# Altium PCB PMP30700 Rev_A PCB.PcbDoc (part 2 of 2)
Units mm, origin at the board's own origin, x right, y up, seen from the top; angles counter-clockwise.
Board outline 118.11 x 43.81 mm, 4 copper layers (Top Layer, Layer 1, Layer 2, Bottom Layer), stack 1.786 mm thick; 113 components, 51 nets, 253 pads, 184 vias.
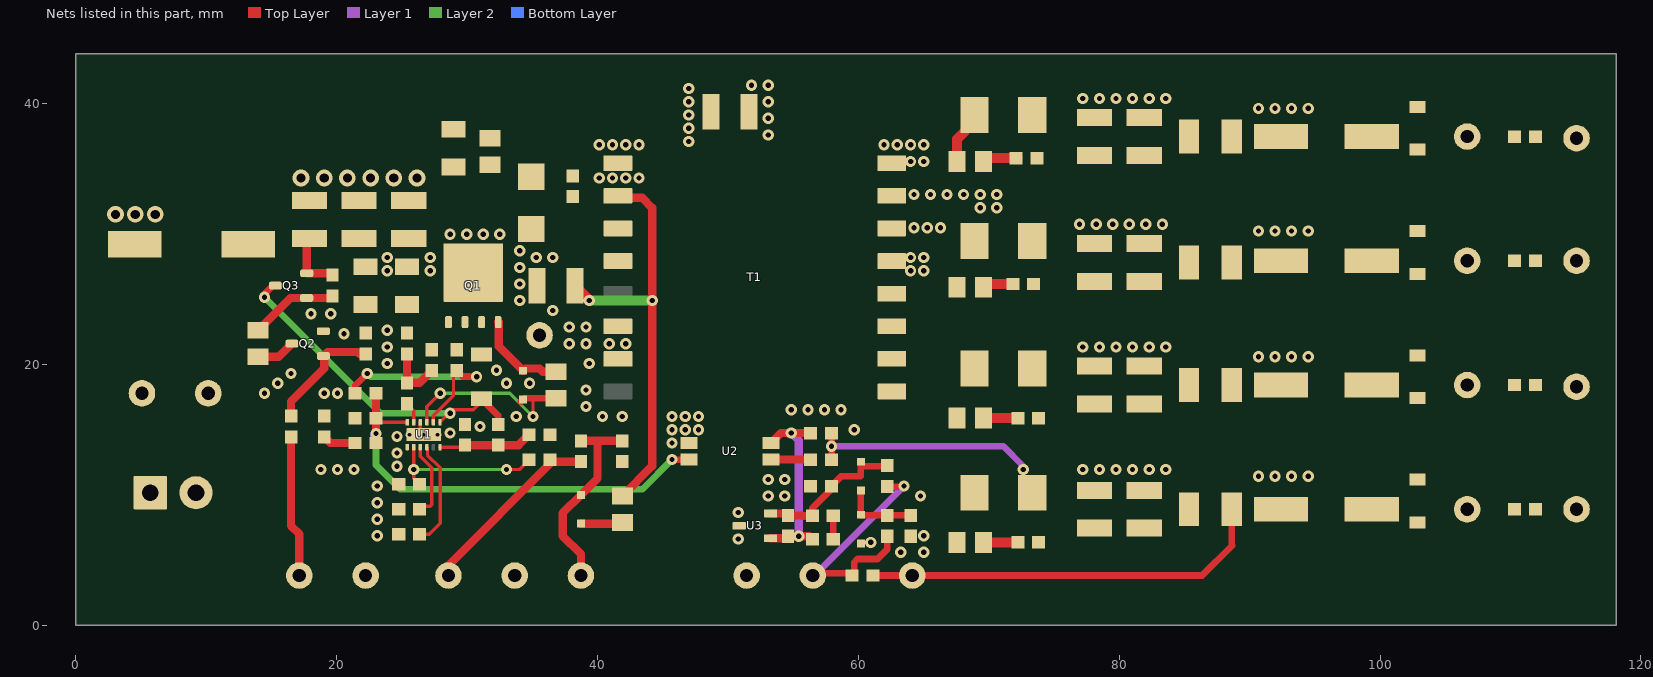
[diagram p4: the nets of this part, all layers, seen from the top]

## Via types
v1: diameter 0.864, hole 0.406, Top Layer to Bottom Layer, 159 vias
v2: diameter 0.864, hole 0.406, Top Layer to Bottom Layer, tented top, 13 vias
v3: diameter 1.27, hole 0.711, Top Layer to Bottom Layer, 9 vias
v4: diameter 0.6, hole 0.3, Top Layer to Bottom Layer, 3 vias

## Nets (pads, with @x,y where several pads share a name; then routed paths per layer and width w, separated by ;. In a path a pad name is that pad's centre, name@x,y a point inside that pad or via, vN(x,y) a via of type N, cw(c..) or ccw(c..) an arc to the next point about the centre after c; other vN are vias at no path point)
GND-P: C11.2 C12.2 C13.2 C14.2 C15.2 C23.2 C24.2 C30.2 C31.2 C32.2 C33.2 C37.2 C38.2 C39.2 J1.1 Q2.2 R12.1 R13.1 R14.1 R17.1 R19.1 R28.1 T1.1 TP1.1 TP14.1 TP16.1 U1.4 U1.7 U1.13@26.67,14.605 U2.3 | length 1.1
  Top Layer w0.254: U1.4@26.42,15.555 26.42,14.795 v4(26.67,14.605)
  other v1: 23.114,6.858 23.114,8.128 23.114,9.398 23.114,10.668 18.796,11.938 20.066,11.938 21.336,11.938 24.638,12.192 24.638,13.208 45.72,13.97 24.638,14.478 28.702,14.732 45.72,14.986 46.736,14.986 47.752,14.986 30.988,15.24 33.782,16.002 40.386,16.002 41.91,16.002 39.116,16.764 14.478,17.78 19.05,17.78 20.066,17.78 39.116,18.034 15.494,18.542 33.02,18.542 16.51,19.304 32.258,19.558 23.876,20.066 23.876,21.336 20.574,22.352 23.876,22.606 18.034,23.876 19.558,23.876 23.876,27.178 27.178,27.178 23.876,28.194 27.178,28.194 40.132,34.29 41.148,34.29 42.164,34.29 43.18,34.29 40.132,36.83 41.148,36.83 42.164,36.83 43.18,36.83 46.99,37.084 46.99,38.1 46.99,39.116 46.99,40.132 46.99,41.148
  other v2: 45.72,16.002 46.736,16.002 47.752,16.002 34.798,18.542
  other v3: 3.048,31.496 4.572,31.496 6.096,31.496 17.272,34.29 19.05,34.29 20.828,34.29 22.606,34.29 24.384,34.29 26.162,34.29
  other v4: 25.595,14.605 27.745,14.605
GND-S1: C2.2 C3.2 C4.2 C5.2 C39.1 D2.2 D15.2 R25.1 R26.1 RTN_1.1 T1.13 TP18.1 U3.3
  other v1: 63.246,5.588 65.024,5.588 60.96,6.35 50.8,6.604 65.024,6.858 50.8,8.636 53.086,9.906 54.356,9.906 64.77,9.906 53.086,11.176 54.356,11.176 90.678,11.43 91.948,11.43 93.218,11.43 94.488,11.43 77.216,11.938 78.486,11.938 79.756,11.938 81.026,11.938 82.296,11.938 83.566,11.938 59.69,14.986 65.024,27.178 65.024,28.194 53.086,37.592 53.086,38.862 53.086,40.132 51.816,41.402 53.086,41.402
  other v2: 54.864,16.51 56.134,16.51 57.404,16.51 58.674,16.51 64.008,27.178 64.008,28.194
NetC1_2: C1.2 R1.2 | length 2.6
  Top Layer w0.762: R1.2@69.596,6.35 C1.2@72.225,6.35
NetC6_1: C6.1 C7.1 C8.1 D3.1 L2.1
NetC6_2: C6.2 R2.2 | length 2.6
  Top Layer w0.762: R2.2@69.596,15.875 C6.2@72.225,15.875
NetC7_2: C7.2 C8.2 C9.2 C10.2 D4.2 RTN_2.1 T1.14
  other v1: 90.678,20.574 91.948,20.574 93.218,20.574 94.488,20.574 77.216,21.336 78.486,21.336 79.756,21.336 81.026,21.336 82.296,21.336 83.566,21.336 64.262,30.48 65.278,30.48 66.294,30.48
NetC9_1: C9.1 C10.1 D4.1 L2.2 OUT_2.1
NetC11_1: C11.1 C12.1 C13.1 C14.1 C15.1 C16.1 J1.2 Q3.2 R3.2 R6.1 T1.3 T1.4 TP5.1 | length 4.8
  Top Layer w0.635: C12.1@17.915,29.665 17.71,29.46 Q3.2@17.71,26.985 19.535,26.985 R6.1@19.685,26.835
NetC16_2: C16.2 D5.1 R3.1
NetC17_1: C17.1 D5.2 Q1.5 Q1.6 Q1.7 Q1.8 Q1.9@30.48,27.04 T1.6 T1.7 TP3.1
  other v1: 39.37,20.066 37.846,21.59 39.116,21.59 40.894,21.59 42.164,21.59 37.846,22.86 39.116,22.86 36.576,24.13 34.036,24.892 34.036,26.162 34.036,27.432 35.306,28.194 36.576,28.194 34.036,28.702 28.702,29.972 29.972,29.972 31.242,29.972 32.512,29.972
NetC17_2: C17.2 R5.2 T1.2 | length 32.7
  Top Layer w0.635: T1.2@41.302,32.92 T1.2@41.57,32.92 41.724,32.766 43.434,32.766 44.196,32.004 v2(44.196,24.892) 44.196,12.192 R5.2@41.91,9.906
  Top Layer w0.762: C17.2@38.28,26.035 39.37,24.945 v1(39.37,24.892)
  Layer 2 w0.762: v1(39.37,24.892) v2(44.196,24.892)
NetC18_1: C18.1 C19.1 C20.1 D6.1 L3.1
NetC18_2: C18.2 R4.2 | length 2.4
  Top Layer w0.762: R4.2@69.596,25.908 69.85,26.162 C18.2@71.844,26.162
NetC19_2: C19.2 C20.2 C21.2 C22.2 D7.2 RTN_3.1 T1.15
  other v1: 90.678,30.226 91.948,30.226 93.218,30.226 94.488,30.226 76.962,30.734 78.232,30.734 79.502,30.734 80.772,30.734 82.042,30.734 83.312,30.734 69.342,32.004 70.612,32.004 64.262,33.02 65.532,33.02 66.802,33.02 68.072,33.02 69.342,33.02 70.612,33.02
NetC21_1: C21.1 C22.1 D7.1 L3.2 OUT_3.1
NetC23_1: C23.1 D8.1 R15.2 TP13.1 | length 15.2
  Top Layer w0.635: TP13.1@38.735,3.81 38.735,5.461 37.338,6.858 37.338,8.593 D8.1@38.735,9.99 40.005,11.26 40.005,14.135 ; R15.2@38.735,14.135 40.005,14.135 ; C23.1@41.91,14.135 40.005,14.135
NetC24_1: C24.1 Q3.3 R7.2 U1.1 | length 25.6
  Top Layer w0.254: U1.1@27.92,15.555 v1@28.661,16.296 ; v1@28.875,16.51 30.48,16.51 31.115,17.145 C24.1@31.115,17.35
  Top Layer w0.508: v1(14.478,25.146) 14.478,25.4 15.113,26.035 Q3.3@15.31,26.035 ; C24.1@31.115,17.35 32.385,16.08 R7.2@32.385,15.405
  Layer 2 w0.508: v1(14.478,25.146) 23.368,16.256 v1(28.702,16.256)
  Bottom Layer w0.381: v1@28.662,16.297 v1(28.702,16.256) v1@28.676,16.23
NetC25_1: C25.1 C26.1 C27.1 D10.1 L4.1
NetC25_2: C25.2 R8.2 | length 2.6
  Top Layer w0.762: R8.2@69.596,35.814 C25.2@72.225,35.814
NetC26_2: C26.2 C27.2 C28.2 C29.2 D11.2 RTN_4.1 T1.16
  other v1: 64.008,35.56 65.024,35.56 61.976,36.83 62.992,36.83 64.008,36.83 65.024,36.83 90.678,39.624 91.948,39.624 93.218,39.624 94.488,39.624 77.216,40.386 78.486,40.386 79.756,40.386 81.026,40.386 82.296,40.386 83.566,40.386
NetC28_1: C28.1 C29.1 D11.1 L4.2 OUT_4.1
NetC31_1: C31.1 R10.1 R18.2 | length 4.5
  Top Layer w0.635: C31.1@25.4,20.79 R18.2@25.4,18.58 26.365,18.58 R10.1@27.305,19.52
NetC32_1: C32.1 R11.1 | length 2.6
  Top Layer w0.635: C32.1@19.05,14.44 19.52,13.97 R11.1@21.425,13.97
NetC33_1: C33.1 R11.2 R23.2 U1.6 U2.4 | length 34
  Top Layer w0.254: C33.1@23.025,15.875 23.345,15.555 U1.6@25.42,15.555
  Top Layer w0.508: v1(45.72,12.7) U2.4@47.015,12.7
  Top Layer w0.635: v2(23.025,14.695) C33.1@23.025,15.875 R23.2@23.025,17.78
  Layer 2 w0.508: v2(23.025,14.695) 23.025,12.281 24.892,10.414 43.434,10.414 v1(45.72,12.7)
  Bottom Layer w0.635: v2@22.86,14.53 v2(23.025,14.695)
NetC34_1: C34.1 R22.2 R27.1 TP19.1 | length 19.4
  Top Layer w0.508: TP19.1@56.515,3.81 56.68,3.975 R27.1@59.69,3.975 ; R27.1@59.525,3.81 R27.1@59.69,3.975 ; C34.1@62.23,6.82 62.23,5.842 61.468,5.08 59.944,5.08 59.69,4.826 R27.1@59.69,3.975 ; R22.2@62.23,10.63 63.462,10.63 v1(63.5,10.668)
  Layer 1 w0.508: TP19.1@56.515,3.81 56.642,3.81 v1(63.5,10.668)
NetC34_2: C34.2 D14.2 D15.1 R25.2 | length 5.7
  Top Layer w0.508: D14.2@60.198,10.33 D15.1@60.198,8.466 60.244,8.42 C34.2@62.23,8.42 R25.2@64.008,8.42
NetC35_1: C35.1 R21.1 R24.1 U2.2 U3.1 | length 14.9
  Top Layer w0.635: U3.1@53.27,6.67 54.46,6.67 C35.1@54.61,6.82 v1(55.435,6.82) 56.261,6.82 R24.1@56.477,6.604 ; U2.2@53.315,13.97 54.077,14.732 v1(54.864,14.732) R21.1@56.35,14.732
  Layer 1 w0.635: v1(54.864,14.732) 55.435,14.16 v1(55.435,6.82)
NetC35_2: C35.2 C36.2 D14.1 R22.1 R26.2 U3.2 | length 11.9
  Top Layer w0.508: C36.2@56.477,8.382 56.477,8.979 57.95,10.452 R26.2@57.95,10.668 58.712,11.43 60.198,11.43 60.198,12.192 ; D14.1@60.198,12.53 60.198,12.192 ; R22.1@62.23,12.23 62.192,12.192 60.198,12.192
  Top Layer w0.635: U3.2@53.27,8.57 54.46,8.57 C35.2@54.61,8.42 55.689,8.42 55.727,8.382 C36.2@56.477,8.382
NetC36_1: C36.1 R24.2 | length 1.8
  Top Layer w0.508: R24.2@58.077,6.604 C36.1@58.077,8.382
NetC37_1: C37.1 R7.1 R12.2 U1.12 | length 7.2
  Top Layer w0.254: U1.12@27.92,13.655 29.695,13.655 C37.1@29.845,13.805
  Top Layer w0.635: C37.1@29.845,13.805 R7.1@32.385,13.805 33.96,13.805 R12.2@34.76,14.605
NetC38_1: C38.1 U1.9 | length 5.9
  Top Layer w0.254: C38.1@26.365,8.89 26.585,9.11 27.192,9.11 27.305,9.223 27.305,12.065 26.42,12.95 U1.9@26.42,13.655
NetD1_2: D1.2 R1.1 T1.9
NetD3_2: D3.2 R2.1 T1.10
NetD6_2: D6.2 R4.1 T1.11
NetD8_2: D8.2 R5.1 | length 3.2
  Top Layer w0.635: D8.2@38.735,7.79 41.826,7.79 R5.1@41.91,7.874
NetD9_1: D9.1 R9.2 U1.3 | length 14.7
  Top Layer w0.254: U1.3@26.92,15.555 26.92,16.76 v1(27.94,17.78) ; v1(35.052,16.002) 35.052,17.386 35.065,17.399
  Top Layer w0.508: D9.1@34.12,17.145 D9.1@34.29,17.315 34.374,17.399 35.065,17.399 R9.2@36.83,17.399
  Layer 2 w0.254: v1(27.94,17.78) 33.274,17.78 v1(35.052,16.002)
NetD9_2: D9.2 Q1.4 R9.1 | length 7.3
  Top Layer w0.635: Q1.4@32.385,23.24 32.433,23.24 32.433,21.373 D9.2@34.29,19.515 34.46,19.685 35.56,19.685 35.814,19.431 R9.1@36.83,19.431
NetD10_2: D10.2 R8.1 T1.12 | length 3.6
  Top Layer w0.762: R8.1@67.564,35.56 67.564,37.262 D10.2@68.91,38.608
NetQ1_1: Q1.1 Q1.2 Q1.3 R10.2 R13.2 R28.2
NetQ2_1: Q2.1 R19.2 R30.1 | length 9.1
  Top Layer w0.635: R30.1@16.51,16.04 16.51,17.145 19.05,19.685 19.05,20.57 Q2.1@18.98,20.64 19.295,20.955 21.59,20.955 21.755,20.79 R19.2@22.225,20.79
NetQ2_3: Q2.3 R29.1 | length 3
  Top Layer w0.635: R29.1@13.97,20.574 15.554,20.574 16.57,21.59 Q2.3@16.58,21.59
NetQ3_1: Q3.1 R6.2 R29.2 | length 6.8
  Top Layer w0.635: R29.2@13.97,22.606 16.449,25.085 Q3.1@17.71,25.085 19.535,25.085 R6.2@19.685,25.235
NetR14_2: R14.2 U1.10 | length 8.2
  Top Layer w0.254: R14.2@26.365,6.985 27.115,6.985 27.94,7.81 27.94,12.072 26.968,13.044 26.968,13.607 U1.10@26.92,13.655
NetR15_1: R15.1 R16.2 TP12.1 | length 14.5
  Top Layer w0.635: TP12.1@28.575,3.81 28.575,4.585 R16.2@36.525,12.535 ; R16.2@36.36,12.7 R16.2@36.525,12.535 ; R15.1@38.735,12.535 R16.2@36.525,12.535
NetR16_1: R16.1 R17.2 U1.8 | length 12.2
  Top Layer w0.254: U1.8@25.92,13.655 v1(25.92,11.938) 25.92,11.24 R17.2@26.365,10.795 ; v1(33.02,11.938) 33.998,11.938 R16.1@34.76,12.7
  Layer 2 w0.254: v1(25.92,11.938) v1(33.02,11.938)
  Bottom Layer w0.254: v1@25.908,11.938 v1(25.92,11.938)
NetR18_1: R18.1 U1.5 | length 1.6
  Top Layer w0.254: R18.1@25.4,16.98 25.92,16.46 U1.5@25.92,15.555
NetR20_1: R20.1 U2.1 | length 3
  Top Layer w0.635: U2.1@53.315,12.7 R20.1@56.35,12.7
NetR30_2: R30.2 TP15.1 | length 10.9
  Top Layer w0.635: R30.2@16.51,14.44 16.51,7.62 17.145,6.985 TP15.1@17.145,3.81
OUT1_SW: C1.1 C2.1 C3.1 D1.1 L1.1 R20.2 R21.2 | length 17.6
  Top Layer w0.508: R20.2@57.95,12.7 v1(57.95,13.716) R21.2@57.95,14.732
  Layer 1 w0.508: v1(57.95,13.716) 71.12,13.716 72.644,12.192 v2(72.644,11.938)
OUT_1: C4.1 C5.1 D2.1 L1.2 OUT_1.1 R27.2 TP17.1 | length 31.3
  Top Layer w0.508: R27.2@61.125,3.81 TP17.1@64.135,3.81 86.36,3.81 88.646,6.096 88.635,6.107 L1.2@88.635,8.89
VCC: C30.1 R23.1 U1.2 | length 16.8
  Top Layer w0.254: U1.2@27.42,15.555 27.422,15.557 27.422,16.049 28.956,17.583 28.956,19.266 C30.1@29.21,19.52
  Top Layer w0.508: R23.1@21.425,17.78 21.425,18.377 v1(22.352,19.304) ; C30.1@29.21,19.52 29.68,19.05 v1(30.734,19.05)
  Layer 2 w0.508: v1(22.352,19.304) 22.606,19.05 v1(30.734,19.05)
pads on no net: Q1.9@29.03,25.655 Q1.9@29.03,27.435 Q1.9@30.48,25.655 Q1.9@30.48,26.585 Q1.9@30.48,27.435 Q1.9@31.93,25.655 Q1.9@31.93,27.435 T1.5 T1.8 U1.11 U1.13@25.985,14.605 U1.13@27.355,14.605

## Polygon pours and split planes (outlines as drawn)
GND-S1 on Top Layer "Top Layer-GND-S1" (solid, pour order 92): 52.324,36.576 51.054,37.846 51.054,42.164 55.88,42.164 56.642,41.402 56.642,22.606 60.452,22.606 60.452,14.478 61.95,12.98 62.955,12.98 65.532,10.403 65.532,2.54 50.038,2.54 49.53,3.048 49.53,9.144 52.324,11.938
NetD1_2 on Top Layer "Top Layer-NetD1_2" (solid, pour order 84): 61.468,18.542 63.754,18.542 64.516,17.78 64.516,14.986 67.31,12.192 70.612,12.192 70.612,8.636 70.104,8.128 68.58,8.128 68.326,7.874 68.326,5.334 66.7,5.334 66.548,5.486 66.548,10.922 61.468,16.002
GND-S1 on Top Layer "Top Layer-GND-S1 2" (solid, pour order 80): 61.468,28.702 65.278,28.702 65.532,28.448 65.532,26.67 64.008,26.67 63.5,27.178 61.468,27.178
NetD3_2 on Top Layer "Top Layer-NetD3_2" (solid, pour order 78): 61.468,21.082 70.866,21.082 71.12,20.828 71.12,17.78 70.866,17.526 68.58,17.526 68.326,17.272 68.326,15.24 68.072,14.986 66.548,14.986 66.548,18.034 65.024,19.558 61.468,19.558
NetD6_2 on Top Layer "Top Layer-NetD6_2" (solid, pour order 76): 61.468,23.622 64.516,23.622 66.802,25.908 66.802,28.194 67.818,29.21 67.818,30.734 71.12,30.734 71.12,27.432 70.866,27.178 68.326,27.178 68.072,26.924 68.072,24.638 65.532,22.098 61.468,22.098
NetD10_2 on Top Layer "Top Layer-NetD10_2" (solid, pour order 74): 69.85,40.64 70.104,40.386 70.104,37.592 69.85,37.338 66.294,37.338 65.532,38.1 60.198,38.1 59.944,37.846 59.944,26.416 60.198,26.162 63.5,26.162 63.5,24.892 58.42,24.892 57.912,25.4 57.912,39.624 58.928,40.64
NetC7_2 on Top Layer "Top Layer-NetC19_2" (solid, pour order 73): 66.802,30.988 66.802,29.718 65.024,29.718 61.468,29.718 61.468,30.988
NetC19_2 on Top Layer "Top Layer-NetC19_2" (solid, pour order 71): 70.866,33.528 71.374,33.02 71.374,31.496 68.58,31.496 67.818,32.258 61.468,32.258 61.468,33.528
NetC26_2 on Top Layer "Top Layer-NetC26_2" (solid, pour order 69): 61.468,34.798 61.468,37.592 65.278,37.592 65.532,37.338 65.532,34.798
NetC26_2 on Top Layer "Top Layer-NetC26_2 1" (solid, pour order 67): 89.916,39.624 90.17,39.37 90.17,36.576 90.424,36.322 94.234,36.322 94.742,36.83 94.742,39.116 95.25,39.624 101.6,39.624 102.108,39.116 104.394,39.116 105.156,39.878 110.49,39.878 111.252,39.116 111.252,34.798 112.014,34.036 116.078,34.036 116.332,34.29 116.332,40.64 115.824,41.148 76.708,41.148 76.2,40.64 76.2,38.1 83.312,38.1 83.566,38.354 83.566,39.116 84.074,39.624
NetC19_2 on Top Layer "Top Layer-NetC19_2 1" (solid, pour order 65): 89.916,29.972 90.17,29.718 90.17,26.924 90.424,26.67 94.234,26.67 94.742,27.178 94.742,29.464 95.25,29.972 101.6,29.972 102.108,29.464 104.394,29.464 105.156,30.226 110.49,30.226 111.252,29.464 111.252,25.146 112.014,24.384 116.078,24.384 116.332,24.638 116.332,30.988 115.824,31.496 76.708,31.496 76.2,30.988 76.2,28.448 83.312,28.448 83.566,28.702 83.566,29.464 84.074,29.972
NetC7_2 on Top Layer "Top Layer-NetC7_2" (solid, pour order 63): 89.916,20.574 90.17,20.32 90.17,17.526 90.424,17.272 94.234,17.272 94.742,17.78 94.742,20.066 95.25,20.574 101.6,20.574 102.108,20.066 104.394,20.066 105.156,20.828 110.49,20.828 111.252,20.066 111.252,15.748 112.014,14.986 116.078,14.986 116.332,15.24 116.332,21.59 115.824,22.098 76.708,22.098 76.2,21.59 76.2,19.05 83.312,19.05 83.566,19.304 83.566,20.066 84.074,20.574
GND-S1 on Top Layer "Top Layer-GND-S1 1" (solid, pour order 47): 89.916,11.176 90.17,10.922 90.17,8.128 90.424,7.874 94.234,7.874 94.742,8.382 94.742,10.668 95.25,11.176 101.6,11.176 102.108,10.668 104.394,10.668 105.156,11.43 110.49,11.43 111.252,10.668 111.252,6.35 112.014,5.588 116.078,5.588 116.332,5.842 116.332,12.192 115.824,12.7 76.708,12.7 76.2,12.192 76.2,9.652 83.312,9.652 83.566,9.906 83.566,10.668 84.074,11.176
NetC28_1 on Top Layer "Top Layer-NetC28_1" (solid, pour order 45): 87.122,38.862 87.376,39.116 89.662,39.116 89.662,36.068 94.996,36.068 95.25,36.322 95.25,38.608 95.758,39.116 101.346,39.116 101.854,38.608 104.648,38.608 105.41,39.37 110.236,39.37 110.744,38.862 110.744,35.56 109.22,34.036 87.63,34.036 87.122,34.544
NetC21_1 on Top Layer "Top Layer-NetC21_1" (solid, pour order 43): 87.122,29.21 87.376,29.464 89.662,29.464 89.662,26.416 94.996,26.416 95.25,26.67 95.25,28.956 95.758,29.464 101.346,29.464 101.854,28.956 104.648,28.956 105.41,29.718 110.236,29.718 110.744,29.21 110.744,25.908 109.22,24.384 87.63,24.384 87.122,24.892
OUT_1 on Top Layer "Top Layer-OUT_1" (solid, pour order 41): 87.122,10.414 87.376,10.668 89.662,10.668 89.662,7.62 94.996,7.62 95.25,7.874 95.25,10.16 95.758,10.668 101.346,10.668 101.854,10.16 104.648,10.16 105.41,10.922 110.236,10.922 110.744,10.414 110.744,7.112 109.22,5.588 87.63,5.588 87.122,6.096
NetC9_1 on Top Layer "Top Layer-NetC9_1" (solid, pour order 39): 87.122,19.812 87.376,20.066 89.662,20.066 89.662,17.018 94.996,17.018 95.25,17.272 95.25,19.558 95.758,20.066 101.346,20.066 101.854,19.558 104.648,19.558 105.41,20.32 110.236,20.32 110.744,19.812 110.744,16.51 109.22,14.986 87.63,14.986 87.122,15.494
NetC25_1 on Top Layer "Top Layer-NetC25_1" (solid, pour order 37): 72.263,40.894 75.565,40.894 75.819,40.64 75.819,37.592 83.947,37.592 84.201,37.846 84.201,38.862 84.455,39.116 86.36,39.116 86.614,38.862 86.614,34.544 86.106,34.036 73.533,34.036 73.279,34.29 73.279,35.814 72.263,36.83
NetC18_1 on Top Layer "Top Layer-NetC18_1" (solid, pour order 35): 72.136,31.547 75.133,31.547 75.692,30.988 75.692,27.94 83.82,27.94 84.074,28.194 84.074,29.21 84.328,29.464 86.36,29.464 86.614,29.21 86.614,24.892 86.106,24.384 73.406,24.384 73.152,24.638 73.152,26.162 72.136,27.178
NetC6_1 on Top Layer "Top Layer-NetC6_1" (solid, pour order 33): 72.263,21.844 75.565,21.844 75.819,21.59 75.819,18.542 83.947,18.542 84.201,18.796 84.201,19.812 84.455,20.066 86.36,20.066 86.614,19.812 86.614,15.494 86.106,14.986 73.533,14.986 73.279,15.24 73.279,16.764 72.263,17.78
OUT1_SW on Top Layer "Top Layer-OUT1_SW" (solid, pour order 31): 72.136,12.446 75.438,12.446 75.692,12.192 75.692,9.144 83.82,9.144 84.074,9.398 84.074,10.414 84.328,10.668 86.106,10.668 86.614,10.16 86.614,6.096 86.106,5.588 73.406,5.588 73.152,5.842 73.152,7.366 72.136,8.382
GND-P on Top Layer "Top Layer-GND-P" (solid, pour order 8): 2.286,28.194 2.286,32.512 6.858,32.512 6.858,28.194
GND-P on Top Layer "Top Layer-GND-P 2" (solid, pour order 22): 49.276,42.164 49.276,37.846 48.26,36.83 48.26,10.922 39.878,2.54 11.938,2.54 11.938,42.164
NetC16_2 on Top Layer "Top Layer-NetC16_2" (solid, pour order 14): 33.528,33.528 33.782,33.274 36.83,33.274 36.576,33.528 36.576,37.846 35.814,38.608 28.194,38.608 28.194,37.338 30.48,37.338 30.48,36.576 32.766,36.576 33.528,35.814
NetC11_1 on Top Layer "Top Layer-NetC11_1" (solid, pour order 12): 33.02,33.528 33.02,35.814 32.512,36.322 30.226,36.322 30.226,42.164 1.524,42.164 1.524,2.54 13.208,2.54 13.208,18.542 12.192,19.558 12.192,24.384 16.002,28.194 19.812,28.194 20.574,28.956 26.416,28.956 27.178,29.718 27.178,30.48 27.94,31.242 32.512,31.242 33.02,31.75 37.592,31.75 37.846,31.496 37.846,29.972 39.624,28.194 39.624,27.432 40.132,26.924 42.672,26.924 43.18,27.432 43.18,31.496 42.926,31.75 40.132,31.75 38.862,33.02 33.528,33.02
NetC17_1 on Top Layer "Top Layer-NetC17_1" (solid, pour order 0): 27.94,30.48 32.766,30.48 33.02,30.734 33.02,30.988 33.528,31.496 36.83,31.496 37.084,31.242 37.084,24.384 37.846,23.622 42.926,23.622 43.18,23.368 43.18,19.812 42.672,19.304 39.116,19.304 38.608,19.812 38.608,20.32 37.846,21.082 34.544,21.082 33.528,22.098 33.528,23.876 32.766,24.638 27.94,24.638
NetQ1_1 on Top Layer "TOP_LAYER_NETQ1_1_P010" (solid, pour order 10): 21.336,26.162 27.178,26.162 27.178,24.13 31.496,24.13 31.496,22.098 27.94,22.098 27.94,20.574 26.924,20.574 26.67,20.828 26.67,23.368 26.416,23.622 21.336,23.622
GND-S1 on Bottom Layer "Bottom Layer-GND-S1" (solid, pour order 61): 52.324,36.83 51.054,38.1 51.054,42.164 59.436,42.164 59.944,41.656 59.944,28.702 65.278,28.702 65.532,28.448 65.532,21.59 74.422,12.7 115.824,12.7 116.332,12.192 116.332,3.048 115.824,2.54 50.038,2.54 49.53,3.048 49.53,9.144 52.315,11.929 52.315,11.995 52.324,12.004
NetC7_2 on Bottom Layer "Bottom Layer-NetC7_2" (solid, pour order 59): 76.2,22.098 67.31,30.988 63.754,30.988 63.754,29.718 65.024,29.718 66.802,27.94 66.802,24.384 76.2,14.986 116.332,14.986 116.586,15.24 116.586,21.59 116.078,22.098
NetC19_2 on Bottom Layer "Bottom Layer-NetC19_2" (solid, pour order 57): 75.692,24.384 68.58,31.496 67.818,32.258 63.754,32.258 63.754,33.528 70.866,33.528 72.898,31.496 115.824,31.496 116.332,30.988 116.332,24.638 116.078,24.384
NetC26_2 on Bottom Layer "Bottom Layer-NetC26_2" (solid, pour order 55): 61.468,34.798 72.771,34.798 73.533,34.036 116.078,34.036 116.332,34.29 116.332,40.64 115.824,41.148 61.468,41.148
NetC17_1 on Bottom Layer "Top Layer-NetC17_1" (solid, pour order 4): 27.94,30.48 32.766,30.48 33.02,30.734 33.02,30.988 33.528,31.496 36.83,31.496 37.084,31.242 37.084,24.384 37.846,23.622 42.926,23.622 43.18,23.368 43.18,19.812 42.672,19.304 39.116,19.304 38.608,19.812 38.608,20.32 37.846,21.082 34.544,21.082 33.528,22.098 33.528,23.876 32.766,24.638 27.94,24.638
GND-P on Bottom Layer "Bottom Layer-GND-P" (solid, pour order 24): 1.524,42.164 48.26,42.164 48.26,20.32 48.26,10.922 39.878,2.54 1.524,2.54
NetC26_2 on Layer 1 "Bottom Layer-NetC26_2" (solid, pour order 102): 61.468,34.798 72.771,34.798 73.533,34.036 116.078,34.036 116.332,34.29 116.332,40.64 115.824,41.148 61.468,41.148
NetC19_2 on Layer 1 "Bottom Layer-NetC19_2" (solid, pour order 100): 75.692,24.384 68.58,31.496 67.818,32.258 63.754,32.258 63.754,33.528 70.866,33.528 72.898,31.496 115.824,31.496 116.332,30.988 116.332,24.638 116.078,24.384
NetC7_2 on Layer 1 "Bottom Layer-NetC7_2" (solid, pour order 98): 76.2,22.098 67.31,30.988 63.754,30.988 63.754,29.718 65.024,29.718 66.802,27.94 66.802,24.384 76.2,14.986 116.332,14.986 116.586,15.24 116.586,21.59 116.078,22.098
GND-S1 on Layer 1 "Bottom Layer-GND-S1" (solid, pour order 96): 52.357,36.784 51.087,38.054 51.087,42.118 59.469,42.118 59.977,41.61 59.977,28.656 65.311,28.656 65.565,28.402 65.565,21.544 74.455,12.654 115.857,12.654 116.365,12.146 116.365,3.002 115.857,2.494 50.071,2.494 49.563,3.002 49.563,9.098 52.348,11.883 52.348,11.949 52.357,11.958
NetC17_1 on Layer 1 "Top Layer-NetC17_1" (solid, pour order 2): 27.94,30.571 32.857,30.571 33.02,30.734 33.02,30.988 33.528,31.496 36.83,31.496 37.084,31.242 37.084,24.384 37.846,23.622 42.926,23.622 43.18,23.368 43.18,19.812 42.672,19.304 39.116,19.304 38.608,19.812 38.608,20.32 37.846,21.082 34.544,21.082 33.528,22.098 33.528,23.876 32.766,24.638 27.94,24.638
GND-P on Layer 1 "LAYER_1_GND-P_P030" (solid, pour order 30): 1.524,42.164 48.26,42.164 48.26,20.32 48.26,10.922 39.878,2.54 1.524,2.54
NetC26_2 on Layer 2 "Layer 2-NetC26_2" (solid, pour order 90): 75.946,40.64 76.454,41.148 115.824,41.148 116.332,40.64 116.332,34.29 116.078,34.036 79.565,34.036 76.009,37.592 75.946,37.592
NetC19_2 on Layer 2 "Layer 2-NetC19_2" (solid, pour order 88): 75.946,30.988 76.454,31.496 115.824,31.496 116.332,30.988 116.332,24.638 116.078,24.384 79.565,24.384 76.009,27.94 75.946,27.94
NetC7_2 on Layer 2 "Layer 2-NetC7_2" (solid, pour order 86): 76.2,21.59 76.708,22.098 116.078,22.098 116.586,21.59 116.586,15.24 116.332,14.986 79.819,14.986 76.263,18.542 76.2,18.542
GND-S1 on Layer 2 "Layer 2-GND-S1" (solid, pour order 82): 52.324,36.916 51.054,38.186 51.054,42.164 59.436,42.164 59.944,41.656 59.944,28.702 63.5,28.702 67.31,28.702 72.898,23.114 72.898,19.05 79.248,12.7 115.824,12.7 116.332,12.192 116.332,3.048 115.824,2.54 50.038,2.54 49.53,3.048 49.53,9.144 52.324,11.938
NetC17_1 on Layer 2 "Top Layer-NetC17_1" (solid, pour order 6): 27.94,30.48 32.766,30.48 33.02,30.734 33.02,30.988 33.528,31.496 36.83,31.496 37.084,31.242 37.084,24.384 37.846,23.622 42.926,23.622 43.18,23.368 43.18,19.812 42.672,19.304 39.116,19.304 38.608,19.812 38.608,20.32 37.846,21.082 34.544,21.082 33.528,22.098 33.528,23.876 32.766,24.638 27.94,24.638

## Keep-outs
Keep-Out Layer:
  text ".Layer_Name" at 14.656,-21.806 h1.52

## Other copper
Top Layer:
  rectangle net GND-P: 16.002,32.004 27.178,35.052
  text ".Layer_Name" at 14.656,-21.806 h1.52
Bottom Layer:
  text ".Layer_Name" at 14.656,-21.806 h1.52

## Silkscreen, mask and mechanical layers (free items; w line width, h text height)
Top Overlay:
  text "-" at 4.572,2.794 h3.05
  text "+" at 8.382,2.794 h3.05
  text "'.PRJ_Number'.PCB_Rev-" at 100.584,2.54 h2.75
  text "A" at 114.046,2.54 h2.03
  text ".Layer_Name" at 14.656,-21.806 h1.52
Bottom Overlay:
  text ".Layer_Name" at 14.656,-21.806 h1.52
Top Paste:
  text ".Layer_Name" at 14.656,-21.806 h1.52
Bottom Paste:
  text ".Layer_Name" at 14.656,-21.806 h1.52
Top Solder:
  text ".Layer_Name" at 14.656,-21.806 h1.52
  text ".Layer_Name" at 14.656,-21.806 h1.52
Bottom Solder:
  text ".Layer_Name" at 14.656,-21.806 h1.52
Drill Guide:
  text ".Layer_Name" at 14.656,-21.806 h1.52
M1 Board Outline:
  the board outline again, w0.254
  text ".Layer_Name" at 14.656,-21.806 h1.52
M2 Board Dimensions:
  rectangle: 0,-6.985 3.175,-3.81
  rectangle: 3.175,-10.16 12.7,-6.985
  lines w0.178: 0,-6.985 25.4,-6.985 ; 3.175,-10.16 3.175,-3.81 ; 6.35,-10.16 6.35,-3.81 ; 12.7,-10.16 12.7,-3.81 ; 19.05,-10.16 19.05,-3.81 ; 0,-10.16 25.4,-10.16 25.4,-3.81 0,-3.81 0,-10.16
  text ".Layer_Name" at 14.656,-21.806 h1.52
M3 3D STEP Top:
  text ".Layer_Name" at 14.656,-21.806 h1.52
M4 3D STEP Bottom:
  text ".Layer_Name" at 14.656,-21.806 h1.52
M5 Assembly Top:
  lines w0.254: -7.417,-23.626 160.223,-23.626 ; -7.417,-18.462 160.274,-18.462 ; -7.417,-13.297 -7.417,-28.791 94.31,-28.791 160.274,-28.791 160.274,-13.297 -7.404,-13.297 -7.404,-28.791 32.614,-28.791 ; 55.194,-28.791 55.194,-13.297 ; 87.376,-18.462 87.376,-13.297 ; 108.712,-18.462 108.712,-13.297 ; 124.511,-28.956 124.511,-23.804
  text "COMPONENTS MARKED 'DNP' SHOULD NOT BE POPULATED." at 29.299,-8.09 h1.52
  text "ASSEMBLY VARIANT:" at 29.286,-11.024 h1.52
  text ".VariantName" at 55.601,-11.024 h1.52
  text "PCB VIEWED FROM TOP SIDE" at -5.804,-16.654 h1.52
  text "BOARD #:" at 57.099,-16.654 h1.52
  text ".PRJ_Number" at 70.955,-16.654 h1.52
  text "REV:" at 92.405,-16.654 h1.52
  text ".PCB_Rev" at 99.809,-16.654 h1.52
  text "SVN REV:" at 113.69,-16.654 h1.52
  text ".VersionControl_RevNumber" at 126.543,-16.654 h1.52
  text "TID #:" at 57.099,-21.819 h1.52
  text ".TID" at 70.955,-21.819 h1.52
  text "PLOT NAME =" at -5.804,-27.034 h1.52
  text ".plot_File_Name" at 14.656,-27.034 h1.52
  text "GENERATED    :" at 57.15,-27.034 h1.52
  text ".Print_Date" at 79.235,-27.034 h1.52
  text ".Print_Time" at 97.752,-27.034 h1.52
  text "TEXAS INSTRUMENTS" at 129.87,-27.034 h1.52
M6 Assembly Bottom:
  lines w0.254: -7.429,-18.474 160.261,-18.474 ; -7.379,-23.639 160.261,-23.639 ; 28.334,-28.969 28.334,-23.817 ; 44.133,-18.474 44.133,-13.31 ; 65.468,-18.474 65.468,-13.31 ; 97.65,-28.804 97.65,-13.31 ; 120.231,-28.804 160.249,-28.804 160.249,-13.31 -7.429,-13.31 -7.429,-28.804 58.534,-28.804 160.261,-28.804 160.261,-13.31
  text "COMPONENTS MARKED 'DNP' SHOULD NOT BE POPULATED." at 154.991,-8.077 h1.52
  text ".VariantName" at 128.473,-11.024 h1.52
  text "ASSEMBLY VARIANT:" at 154.864,-11.024 h1.52
  text ".VersionControl_RevNumber" at 26.302,-16.667 h1.52
  text "SVN REV:" at 39.154,-16.667 h1.52
  text ".PCB_Rev" at 53.035,-16.667 h1.52
  text "REV:" at 60.439,-16.667 h1.52
  text ".PRJ_Number" at 81.89,-16.667 h1.52
  text "BOARD #:" at 95.745,-16.667 h1.52
  text "PCB VIEWED FROM BOTTOM SIDE" at 158.648,-16.667 h1.52
  text ".TID" at 81.89,-21.831 h1.52
  text "TID #:" at 95.745,-21.831 h1.52
  text "TEXAS INSTRUMENTS" at 22.974,-27.047 h1.52
  text ".Print_Time" at 55.093,-27.047 h1.52
  text ".Print_Date" at 73.609,-27.047 h1.52
  text "GENERATED    :" at 95.694,-27.047 h1.52
  text ".plot_File_Name" at 138.189,-27.047 h1.52
  text "PLOT NAME =" at 158.648,-27.047 h1.52
M9 Title Sheet:
  drawing of 57 lines, arcs and shapes, not listed
  text "1" at 18.792,204.127 h1.78
  text "2" at 82.182,204.127 h1.78
  text "3" at 145.411,204.127 h1.78
  text "4" at 209.08,204.127 h1.78
  text "5" at 272.555,204.127 h1.78
  text "6" at 336.182,204.127 h1.78
  text "A" at -10.579,175.095 h1.78
  text "A" at 365.341,175.095 h1.78
  text "B" at -10.579,114.643 h1.78
  text "B" at 365.341,114.643 h1.78
  text "C" at -10.579,54.318 h1.78
  text "C" at 365.341,54.318 h1.78
  text "PROJECT TITLE:" at 288.125,7.048 h1.14
  text ".PRJ_Title" at 289.395,3.662 h1.78
  text "DESIGNED FOR:" at 288.125,-0.597 h1.14
  text ".PRJ_Customer" at 289.395,-4.153 h1.78
  text "D" at -10.579,-5.88 h1.78
  text "D" at 365.341,-5.88 h1.78
  text "FILE NAME:" at 288.125,-8.217 h1.14
  text ".PCB_File_Name_No_Path" at 289.395,-11.265 h1.78
  text "Texas Instruments (TI) and/or its licensors do not warrant the accuracy or completeness of this specification" at 161.9,-15.376 h1.14
  text "ENGINEER:" at 288.125,-15.583 h1.14
  text "LAYOUT BY:" at 326.352,-15.583 h1.14
  text "or any information contained therein. TI and/or its licensors do not warrant that this design will meet" at 160.757,-18.237 h1.14
  text ".PRJ_Engineer" at 289.395,-19.52 h1.78
  text ".PCB_Layout" at 327.635,-19.52 h1.78
  text "the specifications, will be suitable for your application or fit for any particular purpose, or will operate in" at 160.757,-21.099 h1.14
  text ".Layer_Name" at 14.656,-21.806 h1.52
  text "ALTIUM DESIGNER VERSION:" at 326.352,-23.457 h1.14
  text "an implementation. TI and/or its licensors do not warrant that the design is production worthy. You should" at 160.757,-23.961 h1.14
  text "completely validate and test your design implementation to confirm the system functionality for your application." at 161.9,-26.822 h1.14
  text ".print_Scale" at 289.395,-26.843 h1.78
  text ".Application_BuildNumber" at 327.635,-26.843 h1.78
  text "1" at 18.792,-32.093 h1.78
  text "2" at 82.182,-32.093 h1.78
  text "3" at 145.411,-32.093 h1.78
  text "4" at 209.08,-32.093 h1.78
  text "5" at 272.555,-32.093 h1.78
  text "6" at 336.182,-32.093 h1.78
M10 Fab Notes:
  drawing of 189 lines, arcs and shapes, not listed
  text "DESIGN INFORMATION" at 314.503,161.447 h1.52
  text "MIN. TRACK WIDTH:" at 298.131,158.091 h1.52
  text "8" at 325.976,158.091 h1.52
  text "MIL" at 329.907,158.091 h1.52
  text "MIN. CLEARANCE:" at 298.131,154.938 h1.52
  text "0.2" at 324.452,154.938 h1.52
  text "mm" at 329.907,154.938 h1.52
  text "MIN. VIA PAD SIZE:" at 298.131,151.785 h1.52
  text "24" at 325.214,151.785 h1.52
  text "MIL" at 329.907,151.785 h1.52
  text "0.05mm (2MIL)" at 315.784,148.486 h1.52
  text "MINIMUM ANNULAR RING" at 289.769,148.277 h1.52
  text "EXTERNAL" at 333.768,148.277 h1.52
  text "PER" at 294.849,145.48 h1.52
  text "IPC-D-275 CLASS 2 LEVEL C" at 300.437,145.48 h1.52
  text "MIL, HOLES" at 338.238,142.928 h1.52
  text "+/-" at 328.27,142.709 h1.52
  text "+/-" at 349.961,142.709 h1.52
  text "REGISTRATION TOLERANCES:" at 289.769,142.682 h1.52
  text "METAL" at 320.243,142.682 h1.52
  text "5" at 334.879,142.683 h1.52
  text "3" at 356.037,142.683 h1.52
  text "MIL" at 358.99,142.682 h1.52
  text "HOLE SIZE TOLERANCE (UNLESS OTHERWISE SPECIFIED):" at 289.769,140.185 h1.52
  text "+/-" at 349.961,140.112 h1.52
  text "3" at 356.037,140.085 h1.52
  text "MIL" at 358.99,140.085 h1.52
  text "MATERIAL:" at 287.87,136.589 h1.52
  text "FR-4 High Tg" at 312.926,133.324 h1.52
  text "X" at 309.257,133.122 h1.52
  text "FR-408" at 298.563,133.007 h1.52
  text "OTHER" at 336.358,133.007 h1.52
  text "62 MIL (1.6mm) +/-10%" at 306.694,129.374 h1.52
  text "X" at 303.643,129.312 h1.52
  text "THICKNESS:" at 289.769,129.165 h1.52
  text "OTHER" at 339.33,129.165 h1.52
  text "TOLERANCE:" at 289.769,125.652 h1.52
  text "X" at 311.314,125.652 h1.52
  text "ANSI IPC-6012 TYPE 3 CLASS 2" at 315.836,125.652 h1.52
  text "OTHER +/-" at 315.835,121.989 h1.52
  text "BOW & TWIST:" at 289.769,118.302 h1.52
  text "X" at 311.314,118.302 h1.52
  text "ANSI IPC-6012 TYPE 3 CLASS 2" at 315.836,118.302 h1.52
  text "OTHER +/-" at 315.835,114.576 h1.52
  text "DRILLING:" at 287.87,111.258 h1.52
  text "NC_DRILL FILES" at 332.599,108.586 h1.52
  text "REFERENCE:" at 289.769,108.486 h1.52
  text "X" at 306.463,108.484 h1.52
  text "AS SHOWN" at 310.984,108.486 h1.52
  text "X" at 329.348,108.486 h1.52
  text "OTHER" at 340.168,104.873 h1.52
  text "PTH COPPER THICKNESS:" at 289.761,104.783 h1.52
  text "X" at 318.697,104.783 h1.52
  text "20-30 um" at 321.948,104.783 h1.52
  text "BOARD FINISH:" at 287.87,101.034 h1.52
  text "SILKSCREEN:" at 291.812,98.237 h1.52
  text "X" at 316.14,98.237 h1.52
  text "TOP" at 319.112,98.237 h1.52
  text "X" at 329.094,98.237 h1.52
  text "BOTTOM" at 332.091,98.237 h1.52
  text "SILKSCREEN COLOR:" at 291.812,94.295 h1.52
  text "X" at 316.115,94.295 h1.52
  text "WHITE" at 319.112,94.295 h1.52
  text "OTHER" at 332.091,94.295 h1.52
  text "X" at 319.442,90.652 h1.52
  text "GREEN" at 322.439,90.652 h1.52
  text "OTHER" at 338.136,90.652 h1.52
  text "SOLDER RESIST COLOR:" at 291.812,90.477 h1.52
  text "X" at 319.442,86.734 h1.52
  text "MATTE" at 322.439,86.734 h1.52
  text "SEMI-GLOSS" at 338.125,86.717 h1.52
  text "IMMERSION GOLD (ENIG)" at 314.819,82.345 h1.52
  text "ENEPIG" at 348.793,82.162 h1.52
  text "SURFACE FINISH:" at 287.87,82.136 h1.52
  text "X" at 310.298,82.136 h1.52
  text "IMM. TIN/SILVER OR EQUIV" at 296.24,78.649 h1.52
  text "OTHER" at 332.599,78.549 h1.52
  text "ARRAY/PANEL:" at 287.87,74.602 h1.52
  text "CUT AND TRIM PER M1 BOARD OUTLINE" at 314.819,74.393 h1.52
  text "N.C. ROUTE" at 314.819,70.94 h1.52
  text "X" at 332.295,70.94 h1.52
  text "V. SCORE" at 336.816,70.94 h1.52
  text "CERTIFICATION:" at 287.87,67.66 h1.52
  text "MATERIALS AND WORKMANSHIP FOR ALL PCBS" at 306.285,67.66 h1.52
  text "TO MEET OR EXCEED THE REQUIREMENTS OF:" at 306.285,65.271 h1.52
  text "X" at 297.078,62.003 h1.52
  text "ANSI IPC-A-600F CLASS ->" at 300.329,62.003 h1.52
  text "X" at 342.188,62.003 h1.52
  text "2" at 344.982,62.003 h1.52
  text "1" at 336.981,61.965 h1.52
  text "3" at 353.973,61.965 h1.52
  text "X" at 317.702,58.252 h1.52
  text "RoHS" at 320.953,58.252 h1.52
  text "OTHER" at 337.321,58.252 h1.52
  text "PER ORDER" at 347.407,58.252 h1.52
  text "ALL BOARDS MUST MEET OR EXCEED UL94-V0 REQUIREMENTS." at 288.569,54.345 h1.52
  text "PCB MUST BEAR THE UL94V-0 UL REGISTERED MATERIAL ID NUMBER" at 288.569,51.397 h1.52
  text "ADDITIONAL REQUIREMENTS:" at 287.87,47.094 h1.52
  text "MICROSECTION:" at 289.769,44.373 h1.52
  text "YES" at 312.775,44.373 h1.52
  text "REQUIRED" at 334.657,40.707 h1.52
  text "BARE BOARD ELEC. TEST:" at 289.769,40.634 h1.52
  text "NONE" at 322.935,40.634 h1.52
  text "X" at 331.66,40.634 h1.52
  text "PER ORDER" at 349.693,40.634 h1.52
  text "XX MIL VIAS REQUIRE NON-CONDUCTIVE FILL AND PLANARIZE" at 294.04,35.428 h1.5
  text "XX MIL VIAS REQUIRE CONDUCTIVE FILL AND PLANARIZE" at 294.243,32.787 h1.52
  text "OUTER XX MIL TRACES REQUIRE 50 OHM SINGLE-ENDED IMPEDANCE" at 294.218,28.637 h1.47
  text "LAYER 2 & 3 (INNER LAYERS) XX MIL WIDE, XX MIL SPACE / TRACES REQUIRE 100 OHM DIFFERENTIAL IMPEDANCE" at 294.015,22.65 h1.52
  text ".Layer_Name" at 14.656,-21.806 h1.52
M11 Gerber Information:
  lines w0.254: -7.417,-23.626 160.223,-23.626 ; -7.417,-18.462 160.274,-18.462 ; -7.417,-13.297 -7.417,-28.791 94.31,-28.791 160.274,-28.791 160.274,-13.297 -7.404,-13.297 -7.404,-28.791 32.614,-28.791 ; 55.194,-28.791 55.194,-13.297 ; 87.376,-18.462 87.376,-13.297 ; 108.712,-18.462 108.712,-13.297 ; 124.511,-28.956 124.511,-23.804
  text "ALL ARTWORK VIEWED FROM TOP SIDE" at -5.804,-16.654 h1.52
  text "BOARD #:" at 57.099,-16.654 h1.52
  text ".PRJ_Number" at 70.955,-16.654 h1.52
  text "REV:" at 92.405,-16.654 h1.52
  text ".PCB_Rev" at 99.809,-16.654 h1.52
  text "SVN REV:" at 113.69,-16.654 h1.52
  text ".VersionControl_RevNumber" at 126.543,-16.654 h1.52
  text "LAYER NAME =" at -5.804,-21.806 h1.52
  text "TID #:" at 57.099,-21.819 h1.52
  text ".TID" at 70.955,-21.819 h1.52
  text "PLOT NAME =" at -5.804,-27.034 h1.52
  text ".plot_File_Name" at 14.656,-27.034 h1.52
  text "GENERATED    :" at 57.15,-27.034 h1.52
  text ".Print_Date" at 79.235,-27.034 h1.52
  text ".Print_Time" at 97.752,-27.034 h1.52
  text "TEXAS INSTRUMENTS" at 129.87,-27.034 h1.52
M12 Stackup:
  drawing of 295 lines, arcs and shapes, not listed
  text "Layer" at 249.119,193.738 h1.52
  text "Name" at 259.531,193.738 h1.52
  text "Material" at 283.147,193.738 h1.52
  text "Thickness" at 304.985,193.738 h1.52
  text "Constant" at 321.49,193.738 h1.52
  text "Board Layer Stack" at 335.965,193.738 h1.52
  text "Top Overlay" at 259.531,190.69 h1.52
  text "Top Solder" at 259.531,187.642 h1.52
  text "Solder Resist" at 283.147,187.642 h1.52
  text "0.40mil" at 304.985,187.642 h1.52
  text "3.5" at 321.49,187.642 h1.52
  text "1" at 249.119,184.594 h1.52
  text "Top Layer" at 259.531,184.594 h1.52
  text "Copper" at 283.147,184.594 h1.52
  text "1.38mil" at 304.985,184.594 h1.52
  text "Dielectric 1" at 259.531,181.546 h1.52
  text "PP-006" at 283.147,181.546 h1.52
  text "2.80mil" at 304.985,181.546 h1.52
  text "4.1" at 321.49,181.546 h1.52
  text "2" at 249.119,178.498 h1.52
  text "Layer 1" at 259.531,178.498 h1.52
  text "Copper" at 283.147,178.498 h1.52
  text "1.38mil" at 304.985,178.498 h1.52
  text "Dielectric1" at 259.531,175.451 h1.52
  text "FR-4" at 283.147,175.451 h1.52
  text "59.20mil" at 304.985,175.451 h1.52
  text "4.8" at 321.49,175.451 h1.52
  text "3" at 249.119,172.403 h1.52
  text "Layer 2" at 259.531,172.403 h1.52
  text "Copper" at 283.147,172.403 h1.52
  text "1.38mil" at 304.985,172.403 h1.52
  text "Dielectric 2" at 259.531,169.355 h1.52
  text "PP-006" at 283.147,169.355 h1.52
  text "2.80mil" at 304.985,169.355 h1.52
  text "4.1" at 321.49,169.355 h1.52
  text "4" at 249.119,166.306 h1.52
  text "Bottom Layer" at 259.531,166.306 h1.52
  text "Copper" at 283.147,166.306 h1.52
  text "1.38mil" at 304.985,166.306 h1.52
  text "Bottom Solder" at 259.531,163.258 h1.52
  text "Solder Resist" at 283.147,163.258 h1.52
  text "0.40mil" at 304.985,163.258 h1.52
  text "3.5" at 321.49,163.258 h1.52
  text "Bottom Overlay" at 259.531,160.21 h1.52
  text ".Layer_Name" at 14.656,-21.806 h1.52
M13 Component Bodies Top:
  text ".Layer_Name" at 14.656,-21.806 h1.52
M14 Component Bodies Bottom:
  text ".Layer_Name" at 14.656,-21.806 h1.52
M15 Courtyards Top:
  text ".Layer_Name" at 14.656,-21.806 h1.52
M16 Courtyards Bottom:
  text ".Layer_Name" at 14.656,-21.806 h1.52
Drill Drawing:
  circle w0.254: c160.015,107.659 r0.703
  lines w0.254: 159.312,97.469 160.015,97.821 160.718,97.469 160.366,98.172 160.718,98.875 160.015,98.523 159.312,98.875 159.664,98.172 159.312,97.469 ; 159.312,100.983 159.664,100.983 160.015,100.632 160.366,100.983 160.718,100.983 160.366,101.334 160.718,101.686 160.366,101.686 160.015,102.037 159.664,101.686 159.312,101.686 159.664,101.334 159.312,100.983 ; 159.312,103.794 160.718,103.794 160.718,105.199 159.312,105.199 159.312,103.794 ; 159.312,111.524 160.718,111.524 160.015,110.118 159.312,111.524
  lines w0.305: 158.038,96.521 240.136,96.521 ; 158.038,112.332 240.136,112.332 ; 166.624,93.358 166.624,115.494 ; 175.061,93.358 175.061,115.494 ; 191.227,93.358 191.227,115.494 ; 197.811,93.358 197.811,115.494 ; 207.342,93.358 207.342,115.494 ; 225.746,93.358 225.746,115.494 ; 158.038,93.358 240.136,93.358 240.136,115.494 158.038,115.494 158.038,93.358
  text "Symbol" at 159.936,113.281 h1.83
  text "Quantity" at 167.572,113.281 h1.83
  text "Finished Hole Size" at 176.009,113.281 h1.83
  text "Plated" at 192.176,113.281 h1.83
  text "Hole Type" at 198.76,113.281 h1.83
  text "Drill Layer Pair" at 208.291,113.281 h1.83
  text "Hole Tolerance" at 226.694,113.281 h1.83
  text "3" at 167.572,110.118 h1.52
  text "11.81mil (0.300mm)" at 176.009,110.118 h1.52
  text "PTH" at 192.176,110.118 h1.52
  text "Round" at 198.76,110.118 h1.52
  text "Top Layer - Bottom Layer" at 208.291,110.118 h1.52
  text "172" at 167.572,106.956 h1.52
  text "16.00mil (0.406mm)" at 176.009,106.956 h1.52
  text "PTH" at 192.176,106.956 h1.52
  text "Round" at 198.76,106.956 h1.52
  text "Top Layer - Bottom Layer" at 208.291,106.956 h1.52
  text "9" at 167.572,103.794 h1.52
  text "28.00mil (0.711mm)" at 176.009,103.794 h1.52
  text "PTH" at 192.176,103.794 h1.52
  text "Round" at 198.76,103.794 h1.52
  text "Top Layer - Bottom Layer" at 208.291,103.794 h1.52
  text "19" at 167.572,100.632 h1.52
  text "40.00mil (1.016mm)" at 176.009,100.632 h1.52
  text "PTH" at 192.176,100.632 h1.52
  text "Round" at 198.76,100.632 h1.52
  text "Top Layer - Bottom Layer" at 208.291,100.632 h1.52
  text "2" at 167.572,97.469 h1.52
  text "50.00mil (1.270mm)" at 176.009,97.469 h1.52
  text "PTH" at 192.176,97.469 h1.52
  text "Round" at 198.76,97.469 h1.52
  text "Top Layer - Bottom Layer" at 208.291,97.469 h1.52
  text "205 Total" at 167.572,94.307 h1.52
  text ".Layer_Name" at 14.656,-21.806 h1.52
M17 Embedded Cavity:
  text ".Layer_Name" at 14.656,-21.806 h1.52
M18 Embedded Assembly:
  text ".Layer_Name" at 14.656,-21.806 h1.52
M19 Embedded Keepout:
  text ".Layer_Name" at 14.656,-21.806 h1.52

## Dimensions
0,-10.16 to 25.4,-10.16 on M2 Board Dimensions
0,0 to 0,43.815 on M2 Board Dimensions
0,0 to 118.11,0 on M2 Board Dimensions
